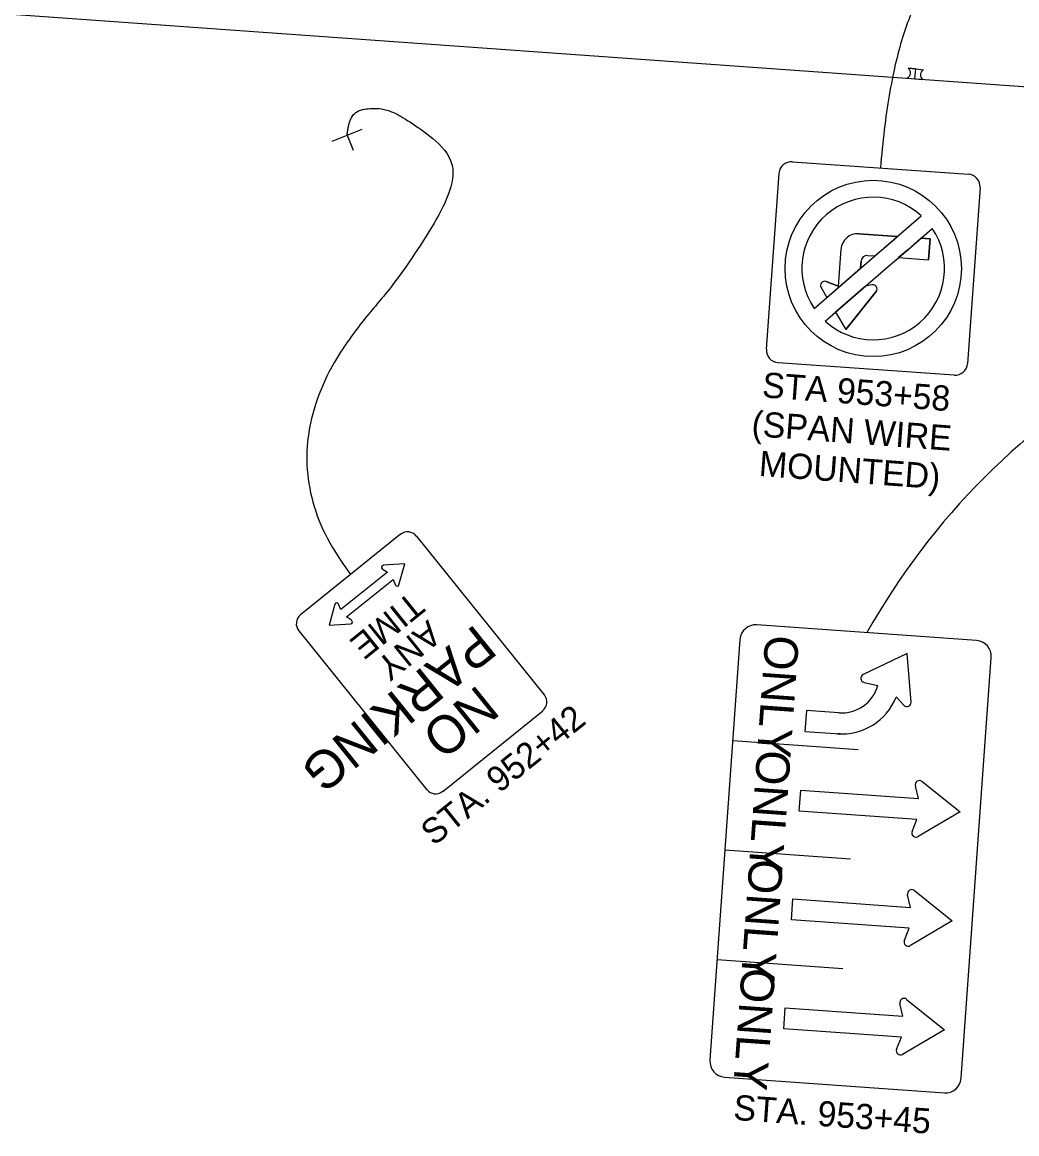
# Model space of a CAD drawing. Extents: x 1847379 to 1850904, y 217032 to 220169.
# Drawn here: x 1849342.9 to 1849441.6, y 218678 to 218788.3 of the extents above; entities that cross this region are included whole.
import ezdxf

# ---------------------------------------------------------------- set-up
doc = ezdxf.new("R2010")
doc.units = 0
for name, color, linetype in [('PM_P_Cells', 7, 'Continuous'), ('PM_P_Edge_Line', 7, 'Continuous'), ('SN_X_Public', 7, 'Continuous'), ('SN_X_Text', 7, 'Continuous')]:
    doc.layers.add(name, color=color, linetype=linetype)

msp = doc.modelspace()

# ---------------------------------------------------------------- linework, layer by layer
at = {"layer": 'PM_P_Cells'}
for p, q in [((1849430.76, 218782.75), (1849431.52, 218782.68)), ((1849430.76, 218782.75), (1849431.52, 218782.68)), ((1849431.61, 218783.65), (1849430.84, 218783.72)), ((1849430.84, 218783.72), (1849431.61, 218783.65)), ((1849431.52, 218782.68), (1849431.61, 218783.65)), ((1849431.52, 218782.68), (1849432.29, 218782.61)), ((1849431.61, 218783.65), (1849432.38, 218783.58))]:
    msp.add_line(p, q, dxfattribs=at)
for centre, start, end in [((1849430.5, 218783.26), 296.8063, 52.8586), ((1849430.5, 218783.26), 296.8063, 52.8586), ((1849432.64, 218783.07), 116.8063, 232.8586)]:
    msp.add_arc(centre, 0.576, start, end, dxfattribs=at)
at = {"layer": 'PM_P_Edge_Line'}
msp.add_line((1848953.55, 218816.79), (1849519.44, 218776.41), dxfattribs=at)
at = {"layer": 'SN_X_Public'}
for p, q in [((1849373.69, 218776.47), (1849376.65, 218777.67)), ((1849375.17, 218777.07), (1849375.77, 218775.59)), ((1849421.52, 218759.88), (1849432.15, 218769.09)), ((1849425.95, 218767.3), (1849429.77, 218767.02)), ((1849429.77, 218767.02), (1849425.95, 218767.3)), ((1849427.54, 218765.1), (1849429.71, 218766.97)), ((1849429.71, 218766.97), (1849429.77, 218767.02)), ((1849432.12, 218766.86), (1849430.8, 218765.71)), ((1849432.12, 218766.86), (1849433.02, 218766.79)), ((1849433.02, 218766.79), (1849432.12, 218766.86)), ((1849433.02, 218766.79), (1849432.87, 218764.71)), ((1849432.87, 218764.71), (1849433.02, 218766.79)), ((1849424.17, 218765.75), (1849423.91, 218762.08)), ((1849424.17, 218765.75), (1849423.91, 218762.08)), ((1849426.82, 218765.15), (1849427.54, 218765.1)), ((1849426.82, 218765.15), (1849427.54, 218765.1)), ((1849430.8, 218765.71), (1849429.89, 218764.93)), ((1849426.18, 218764.59), (1849426.13, 218763.87)), ((1849426.13, 218763.87), (1849426.18, 218764.59)), ((1849429.89, 218764.93), (1849432.87, 218764.71)), ((1849429.89, 218764.93), (1849432.87, 218764.71)), ((1849422.78, 218760.97), (1849426.13, 218763.87)), ((1849422.2, 218761.95), (1849422.78, 218760.97)), ((1849422.2, 218761.95), (1849422.78, 218760.97)), ((1849422.71, 218762.55), (1849423.91, 218762.08)), ((1849423.91, 218762.08), (1849422.71, 218762.55)), ((1849426.61, 218762.08), (1849423.64, 218759.51)), ((1849427.24, 218762.23), (1849426.62, 218762.08)), ((1849427.24, 218762.23), (1849426.62, 218762.08)), ((1849427.66, 218761.56), (1849424.65, 218757.78)), ((1849424.65, 218757.78), (1849427.66, 218761.56)), ((1849423.64, 218759.51), (1849424.65, 218757.78)), ((1849423.64, 218759.51), (1849424.65, 218757.78)), ((1849380.91, 218734.53), (1849378.75, 218734.39)), ((1849380.31, 218732.45), (1849380.91, 218734.53)), ((1849378.66, 218734.05), (1849379.16, 218733.72)), ((1849375.12, 218729.26), (1849379.75, 218732.99)), ((1849379.75, 218732.99), (1849379.74, 218732.99)), ((1849379.75, 218732.99), (1849379.97, 218732.43)), ((1849376.95, 218731.71), (1849376.95, 218731.71)), ((1849373.96, 218730.53), (1849373.37, 218728.45)), ((1849374.53, 218729.99), (1849374.31, 218730.54)), ((1849375.61, 218728.93), (1849375.12, 218729.26)), ((1849375.12, 218729.26), (1849375.12, 218729.26)), ((1849373.37, 218728.45), (1849375.52, 218728.59)), ((1849430.76, 218725.63), (1849426.39, 218723.55)), ((1849431.14, 218720.81), (1849430.76, 218725.63)), ((1849426.48, 218722.77), (1849427.85, 218722.46)), ((1849429.66, 218721.32), (1849430.41, 218720.5)), ((1849420.75, 218719.98), (1849420.6, 218717.9)), ((1849423.97, 218719.75), (1849420.75, 218719.98)), ((1849420.6, 218717.9), (1849424.09, 218717.65)), ((1849424.09, 218717.65), (1849423.82, 218717.66)), ((1849413.43, 218717), (1849425.9, 218716.11)), ((1849420.04, 218710), (1849420.19, 218712.08)), ((1849420.19, 218712.08), (1849431.86, 218711.25)), ((1849431.86, 218711.25), (1849431.56, 218712.5)), ((1849432.23, 218712.92), (1849436, 218709.91)), ((1849431.71, 218709.17), (1849420.04, 218710)), ((1849436, 218709.91), (1849431.84, 218707.46)), ((1849431.24, 218707.97), (1849431.71, 218709.17)), ((1849412.66, 218706.14), (1849425.13, 218705.25)), ((1849419.27, 218699.2), (1849419.41, 218701.28)), ((1849419.41, 218701.28), (1849431.09, 218700.44)), ((1849431.09, 218700.44), (1849430.79, 218701.7)), ((1849431.46, 218702.12), (1849435.23, 218699.1)), ((1849430.94, 218698.37), (1849419.27, 218699.2)), ((1849435.23, 218699.1), (1849431.07, 218696.65)), ((1849430.47, 218697.17), (1849430.94, 218698.37)), ((1849411.89, 218695.28), (1849424.35, 218694.39)), ((1849430.68, 218691.31), (1849434.46, 218688.3)), ((1849418.5, 218688.39), (1849418.64, 218690.47)), ((1849418.64, 218690.47), (1849430.32, 218689.64)), ((1849430.32, 218689.64), (1849430.02, 218690.89)), ((1849430.17, 218687.56), (1849418.5, 218688.39)), ((1849434.46, 218688.3), (1849430.3, 218685.85)), ((1849429.7, 218686.36), (1849430.17, 218687.56))]:
    msp.add_line(p, q, dxfattribs=at)
for points in [[(1849419.36, 218774.45), (1849436.82, 218773.21)], [(1849416.78, 218755.84), (1849418.03, 218773.29)], [(1849437.98, 218771.87), (1849436.73, 218754.41)], [(1849430.8, 218765.71), (1849433.24, 218767.83)], [(1849422.61, 218758.62), (1849428.63, 218763.84), (1849430.8, 218765.71)], [(1849426.62, 218762.08), (1849426.61, 218762.08)], [(1849435.4, 218753.26), (1849417.94, 218754.5)], [(1849380.46, 218737.47), (1849370.53, 218729.47)], [(1849394.75, 218721.53), (1849382.04, 218737.3)], [(1849379.16, 218733.72), (1849374.53, 218729.99)], [(1849370.36, 218727.89), (1849383.07, 218712.12)], [(1849437.64, 218726.92), (1849415.82, 218728.47)], [(1849414.15, 218727.03), (1849411.17, 218685.26)], [(1849436.11, 218683.48), (1849439.09, 218725.25)], [(1849384.65, 218711.95), (1849394.58, 218719.95)], [(1849412.62, 218683.59), (1849434.44, 218682.03)]]:
    msp.add_lwpolyline(points, dxfattribs=at)
msp.add_circle((1849427.38, 218763.85), 8.75, dxfattribs=at)
for centre, radius, start, end in [((1849419.27, 218773.2), 1.25, 85.9213, 175.9213), ((1849436.73, 218771.96), 1.25, 355.9213, 85.9213), ((1849427.38, 218763.85), 7.08, 47.6777, 214.165), ((1849427.38, 218763.85), 7.08, 227.6777, 34.165), ((1849427.38, 218763.85), 7.08, 227.6777, 34.165), ((1849425.84, 218765.63), 1.67, 85.9213, 175.9213), ((1849425.84, 218765.63), 1.67, 85.9213, 175.9213), ((1849426.78, 218764.55), 0.6, 85.9213, 175.9213), ((1849426.78, 218764.55), 0.6, 85.9213, 175.9213), ((1849488.85, 218692.79), 71.24, 88.6045, 150.6957), ((1849422.56, 218762.16), 0.417, 68.5595, 210.4376), ((1849422.56, 218762.16), 0.417, 68.5595, 210.4376), ((1849427.34, 218761.82), 0.417, 321.4051, 103.2832), ((1849427.34, 218761.82), 0.417, 321.4051, 103.2832), ((1849418.03, 218755.75), 1.25, 175.9213, 265.9213), ((1849435.49, 218754.5), 1.25, 265.9213, 355.9213), ((1849381.16, 218736.59), 1.12, 38.8676, 128.8676), ((1849378.76, 218734.2), 0.182, 93.7884, 236.5054), ((1849380.14, 218732.5), 0.182, 201.2298, 343.9469), ((1849374.14, 218730.48), 0.182, 21.2298, 163.9469), ((1849371.24, 218728.59), 1.12, 128.8676, 218.8676), ((1849375.51, 218728.77), 0.182, 273.7884, 56.5054), ((1849415.71, 218726.92), 1.56, 85.9213, 175.9213), ((1849437.53, 218725.36), 1.56, 355.9213, 85.9213), ((1849426.57, 218723.18), 0.417, 115.4286, 257.3067), ((1849424.24, 218723.49), 3.75, 265.9213, 344.1446), ((1849393.87, 218720.83), 1.12, 308.8676, 38.8676), ((1849424.24, 218723.49), 5.84, 265.9213, 338.1533), ((1849430.72, 218720.78), 0.417, 222.583, 4.4611), ((1849383.94, 218712.83), 1.12, 218.8676, 308.8676), ((1849431.97, 218712.6), 0.417, 51.4051, 193.2832), ((1849431.63, 218707.82), 0.417, 158.5595, 300.4376), ((1849431.2, 218701.79), 0.417, 51.4051, 193.2832), ((1849430.85, 218697.01), 0.417, 158.5595, 300.4376), ((1849430.43, 218690.99), 0.417, 51.4051, 193.2832), ((1849430.08, 218686.21), 0.417, 158.5595, 300.4376), ((1849412.73, 218685.15), 1.56, 175.9213, 265.9213), ((1849434.55, 218683.59), 1.56, 265.9213, 355.9213)]:
    msp.add_arc(centre, radius, start, end, dxfattribs=at)
at = {"layer": 'SN_X_Text'}
for points in [[(1849494.67, 218818.75), (1849500.66, 218818.68), (1849506.53, 218812.81), (1849502.68, 218794.1), (1849444.39, 218796.58), (1849429.74, 218793.85), (1849428.09, 218773.83)], [(1849375.17, 218777.07), (1849375.34, 218779.07), (1849377.22, 218779.88), (1849380.32, 218779.44), (1849388.65, 218772.75), (1849366, 218745.95), (1849375.5, 218733.47)]]:
    msp.add_open_spline(points, degree=2, dxfattribs=at)

# ---------------------------------------------------------------- texts
at = {"layer": 'SN_X_Public'}
for s, height, rotation, p in [('TIME', 2.5, 218.8676, (1849381.49, 218731.88)), ('ANY', 2.5, 218.8676, (1849383.2, 218729.04)), ('PARKING', 3.75, 218.8676, (1849387.91, 218728.63)), ('ONLY', 3.333, 265.9213, (1849416.69, 218727.53)), ('NO', 3.75, 218.8676, (1849388.17, 218722.61)), ('ONLY', 3.333, 265.9213, (1849415.88, 218716.13)), ('ONLY', 3.333, 265.9213, (1849415.11, 218705.32)), ('ONLY', 3.333, 265.9213, (1849414.34, 218694.51))]:
    msp.add_text(s, height=height, rotation=rotation, dxfattribs=at).set_placement(p)
at = {"layer": 'SN_X_Text'}
for s, rotation, p in [('STA 953+58', 355.7486, (1849416.3, 218751.07)), ('(SPAN WIRE ', 355.7486, (1849415.25, 218747.23)), ('MOUNTED)', 355.7486, (1849415.98, 218743.27)), ('STA. 952+42', 38.8676, (1849383.77, 218706.47)), ('STA. 953+45', 355.9213, (1849413.45, 218679.36))]:
    msp.add_text(s, height=2.5, rotation=rotation, dxfattribs=at).set_placement(p)

doc.saveas('drawing.dxf')
